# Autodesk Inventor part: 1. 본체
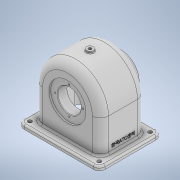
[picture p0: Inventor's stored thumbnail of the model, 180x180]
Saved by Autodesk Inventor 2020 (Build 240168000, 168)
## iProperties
Created: 2022-09
Part Number: 1. 본체
Material: 일반
Document SubType Name: Modeling
Designer: Administrator
Density: 1 g/cm^3
Appearance: 기본값
Author: Administrator
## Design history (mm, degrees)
sketch "스케치2" dims "d0" = 114
  geometry: L1 (-57, 64)-(57, 64); L2 (57, 64)-(57, 0); L3 (57, 0)-(-57, 0); L4 (-57, 0)-(-57, 64); 4 further points
  constraints: 8 end point, 2 parallel, 2 vertical, 1 horizontal, 1 horizontal alignment, 1 midpoint, 1 perpendicular, 3 other
  dimensions: "d1" = 64 distance of point (0, 64) point (0, 0); "d18" = 64 distance between parallel lines of L1 L3
extrude "돌출1" new body sketch "스케치2" distance "d2" = 78; taper "d3" = 0 deg
fillet "모깎기1" dims "d4" = 14
feature "쉘1" dims "d5" = 5
sketch "스케치3"
  geometry: L1 (-70, 15)-(70, 15); L2 (70, 15)-(70, -93); L3 (70, -93)-(-70, -93); L4 (-70, -93)-(-70, 15); L5 (-57, -14)-(-57, -64) reference; L6 (43, 0)-(-43, 0) reference; L7 (43, 0)-(-43, 0) reference; L8 (57, -14)-(57, -64) reference; L9 (57, -14)-(57, -64) reference; L10 (43, -78)-(-43, -78) reference; A1 r 14 centre (-43, -14) between (-43, 0) and (-57, -14) reference; A2 r 14 centre (-43, -14) between (-43, 0) and (-57, -14) reference; A3 r 14 centre (43, -14) between (57, -14) and (43, 0) reference; A4 r 14 centre (43, -14) between (57, -14) and (43, 0) reference; A5 r 14 centre (43, -64) between (43, -78) and (57, -64) reference; A6 r 14 centre (-43, -64) between (-57, -64) and (-43, -78) reference; 8 further points
  constraints: 8 end point, 3 midpoint, 2 parallel, 1 horizontal, 1 horizontal alignment, 1 perpendicular, 1 vertical alignment
  dimensions: "d6" = 108 distance of L3.end L1.start; "d7" = 140 distance of L1.start L1.end
extrude "돌출2" join sketch "스케치3" distance "d8" = 7; taper "d9" = 0 deg
fillet "모깎기2" dims "d10" = 10
sketch "스케치5"
  geometry: A1 r 10 centre (-60, 83) between (-60, 93) and (-70, 83) reference; A2 r 10 centre (-60, -5) between (-70, -5) and (-60, -15) reference; A3 r 10 centre (60, -5) between (60, -15) and (70, -5) reference; A4 r 10 centre (60, 83) between (70, 83) and (60, 93) reference; 5 further points
  constraints: 4 coincident
hole "구멍1" sketch "스케치5" at (-60, 83), (-60, -5), (60, -5), (60, 83) diameter "d11" = 6.6; stored, may be unused: countersink angle "d15" = 90 deg, drill point angle "d17" = 118 deg; dims "d12" = 6, "d13" = 4, "d14" = 2, "d16" = 8
node "작업 평면1"
sketch "스케치6"
  geometry: L1 (3, 79)-(3, 29) reference; C1 r 6 at (60, 54); 2 further points
  constraints: 1 centre point, 1 horizontal alignment, 1 midpoint, 1 vertical alignment
  dimensions: "d20" = 12 diameter of C1
extrude "돌출3" join sketch "스케치6" stored distance "d21" = 7; taper "d22" = 0 deg
sketch "스케치7"
  geometry: C1 r 6 at (0, 0) reference; 2 further points
  constraints: 1 coincident
hole "구멍2" sketch "스케치7" at (0, 0) diameter "d23" = 5.1881; stored, may be unused: countersink angle "d27" = 90 deg, drill point angle "d29" = 118 deg; dims "d24" = 12, "d25" = 4, "d26" = 2, "d28" = 16
sketch "스케치8"
  geometry: A1 r 43 centre (0, 64) between (43, 64) and (-43, 64) reference; 2 further points
  constraints: 1 coincident
hole "구멍3" sketch "스케치8" at (0, 64) diameter "d30" = 64; stored, may be unused: countersink angle "d34" = 90 deg, drill point angle "d36" = 0 deg; dims "d31" = 12, "d32" = 4, "d33" = 2, "d35" = 3
sketch "스케치9"
  geometry: C1 r 31 at (0, 64); A1 r 43 centre (0, 64) between (43, 64) and (-43, 64) reference; 1 further point
  constraints: 1 centre point, 1 coincident
  dimensions: "d37" = 62 diameter of C1
extrude "돌출4" join sketch "스케치9" distance "d38" = 15; taper "d39" = 0 deg
sketch "스케치10"
  geometry: C1 r 31 at (0, 0) reference; 2 further points
  constraints: 1 coincident
hole "구멍4" sketch "스케치10" at (0, 0) diameter "d40" = 40; stored, may be unused: countersink angle "d44" = 90 deg, drill point angle "d46" = 0 deg; dims "d41" = 12, "d42" = 4, "d43" = 2, "d45" = 16
sketch "스케치11"
  geometry: C1 r 20 at (0, 0) reference; 2 further points
  constraints: 1 coincident
hole "구멍5" sketch "스케치11" at (0, 0) diameter "d47" = 35; stored, may be unused: countersink angle "d51" = 90 deg, drill point angle "d53" = 0 deg; dims "d48" = 12, "d49" = 4, "d50" = 2, "d52" = 16
sketch "스케치12"
  geometry: C1 r 31 at (0, 0) reference; A1 r 24 centre (0, 0) between (0, 24) and (-24, 0); 3 further points
  constraints: 4 point on circle, 1 centre point, 1 coincident
  dimensions: "d54" = 48 diameter of A1
hole "구멍6" sketch "스케치12" at (0, 24), (-24, 0), (0, -24), (24, 0) diameter "d55" = 2.459; stored, may be unused: countersink angle "d59" = 90 deg, drill point angle "d61" = 118 deg; dims "d56" = 7, "d57" = 4, "d58" = 2, "d60" = 9
node "작업 평면2"
node "작업 평면3"
sketch "스케치13"
  geometry: C1 r 28 at (0, 0); A1 r 43 centre (0, 0) between (43, 0) and (-43, 0) reference; 1 further point
  constraints: 1 centre point, 1 coincident, 1 vertical alignment
  dimensions: "d63" = 56 diameter of C1
extrude "돌출5" join sketch "스케치13" stored distance "d64" = 15; taper "d65" = 60 deg
sketch "스케치14"
  geometry: C1 r 32 at (0, 0) reference; 2 further points
  constraints: 1 coincident
hole "구멍7" sketch "스케치14" at (0, 0) diameter "d66" = 40; stored, may be unused: countersink angle "d70" = 90 deg, drill point angle "d72" = 0 deg; dims "d67" = 7, "d68" = 4, "d69" = 2, "d71" = 9
fillet "모깎기3" dims "d73" = 3, "d74" = 1, "d75" = 0.6
chamfer "모따기1" distance "d76" = 1; stored, may be unused: second distance "d77" = 2, angle "d78" = 45 deg
sketch "스케치15"
  geometry: L1 (-19, -64)-(69, -64) reference; L2 (-29, -60)-(-29, -64) reference; L3 (-14, 0)-(-14, -54) reference; L4 (5.304, -41.167)-(44.696, -41.167); L5 (44.696, -41.167)-(44.696, -52.833); L6 (44.696, -52.833)-(5.304, -52.833); L7 (5.304, -52.833)-(5.304, -41.167); 1 further point
  constraints: 2 other
feature "엠보싱1" sketch "스케치15" dims "d6" = 108, "d7" = 140, "d82" = 0.5, "d83" = 0
node "솔리드1"
mirror "미러1"
node "투영된 루프1"
node "투영된 루프2"
node "투영된 루프3"
node "투영된 루프4"
feature "A9D066F2-1C7D-4E18-AEED-F7BC21143FA4" dims "d11" = 6.6, "d12" = 6, "d13" = 4, "d14" = 2, "d15" = 90 deg, "d16" = 8, "d17" = 118 deg
other parameters: "d19" = -124, "d62" = 14
